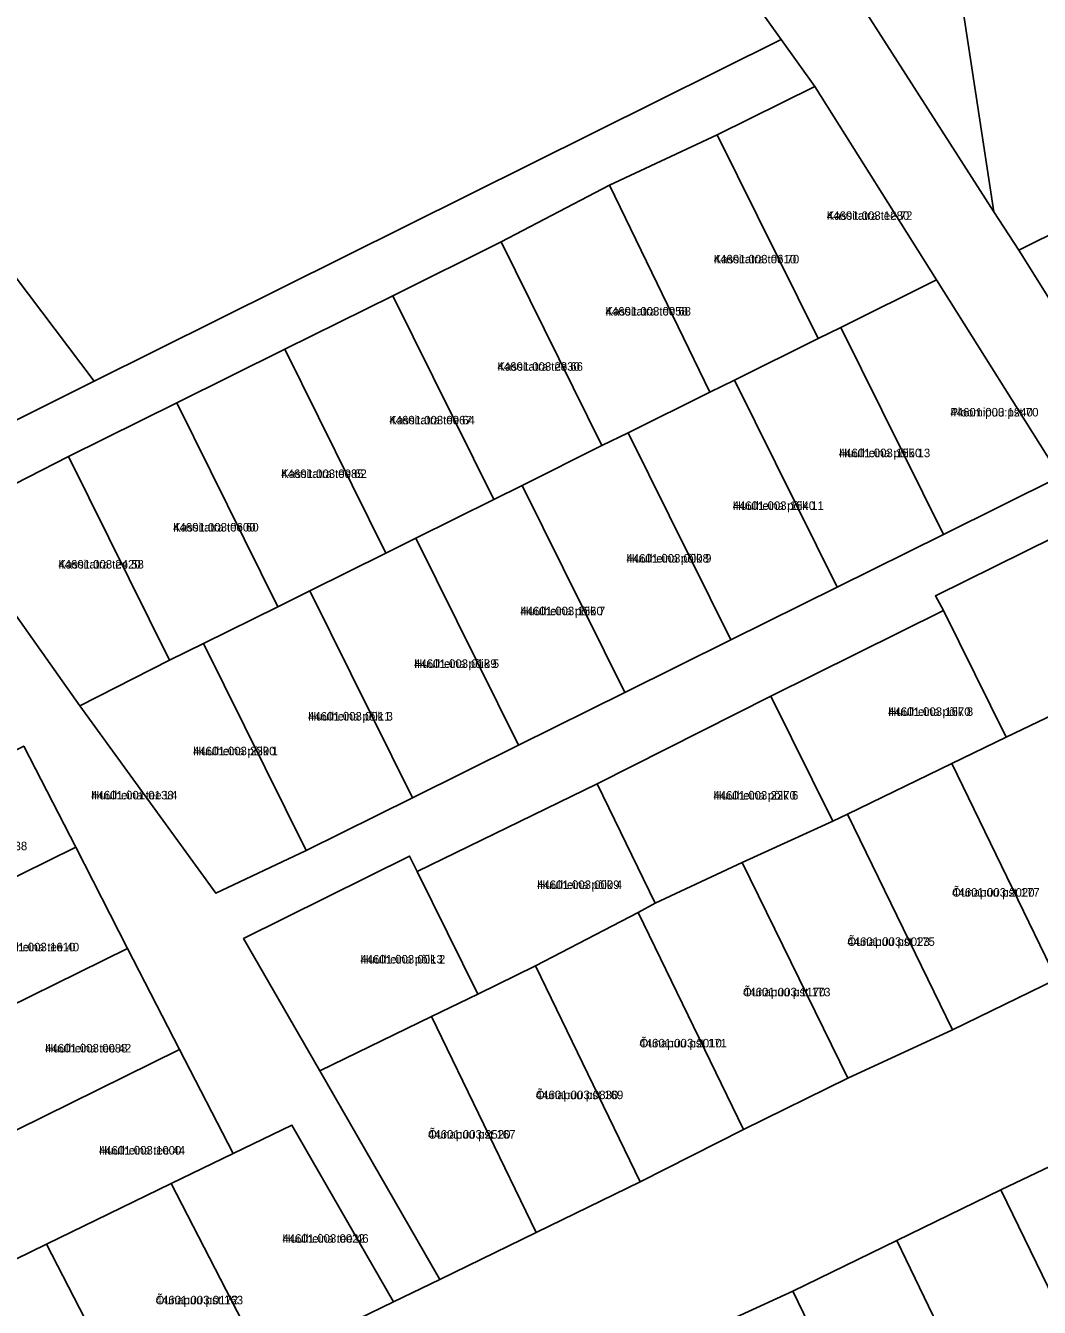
# Model space of a CAD drawing. Extents: x 551843 to 558501, y 6589003 to 6595718.
# Drawn here: x 553719.3 to 553897.7, y 6593355.7 to 6593581.1 of the extents above; entities that cross this region are included whole.
import ezdxf

# ---------------------------------------------------------------- set-up
doc = ezdxf.new("R2010")
doc.units = 0
for name, color, linetype in [('L_AADRESS', 7, 'Continuous'), ('PIIR', 7, 'Continuous'), ('TUNNUS', 7, 'Continuous')]:
    doc.layers.add(name, color=color, linetype=linetype)

msp = doc.modelspace()

# ---------------------------------------------------------------- linework, layer by layer
at = {"layer": 'PIIR'}
for points in [[(553642.95, 6593640.9), (553651.15, 6593647.15), (553652.31, 6593645.45), (553665.73, 6593654.61), (553682.25, 6593665.88), (553706.18, 6593691.1), (553727.55, 6593666.75), (553740.49, 6593651.51), (553753.74, 6593636.43), (553762.31, 6593626.44), (553803.44, 6593644.47), (553829.2, 6593610.91), (553852.28, 6593578.7), (553731.4, 6593518.62), (553696.7, 6593564.49), (553681.11, 6593583.74), (553684.34, 6593586.4), (553671.35, 6593603.22), (553668.55, 6593601.29), (553655.51, 6593620.23)], [(553910.99, 6593550.05), (553894.06, 6593541.63), (553889.7, 6593548.41), (553884.42, 6593582.9), (553904.35, 6593593.35)], [(553840.98, 6593561.94), (553858.18, 6593570.46), (553879.59, 6593536.42), (553862.74, 6593528.08), (553858.75, 6593526.1)], [(553696.7, 6593564.49), (553731.4, 6593518.62), (553702.86, 6593504.37), (553697.19, 6593505.23), (553669, 6593541.5)], [(553840.98, 6593561.94), (553858.75, 6593526.1), (553844.05, 6593518.81), (553839.73, 6593516.67), (553822.04, 6593553.06)], [(553894.06, 6593541.63), (553910.99, 6593550.05), (553915.92, 6593552.49), (553934.2, 6593561.55), (553942.87, 6593544.12), (553904.46, 6593525.08)], [(553802.98, 6593543.1), (553822.04, 6593553.06), (553839.73, 6593516.67), (553825.36, 6593509.55), (553820.74, 6593507.32)], [(553802.98, 6593543.1), (553820.74, 6593507.32), (553806.68, 6593500.28), (553801.7, 6593497.81), (553783.93, 6593533.64)], [(553862.74, 6593528.08), (553879.59, 6593536.42), (553901.33, 6593501.86), (553880.8, 6593491.68)], [(553764.93, 6593524.22), (553783.93, 6593533.64), (553801.7, 6593497.81), (553788, 6593491.02), (553782.7, 6593488.39)], [(553858.75, 6593526.1), (553862.74, 6593528.08), (553880.8, 6593491.68), (553862.11, 6593482.42), (553844.05, 6593518.81)], [(553763.69, 6593478.96), (553745.92, 6593514.79), (553764.93, 6593524.22), (553782.7, 6593488.39), (553769.33, 6593481.76)], [(553825.36, 6593509.55), (553839.73, 6593516.67), (553844.05, 6593518.81), (553862.11, 6593482.42), (553843.43, 6593473.16)], [(553726.89, 6593505.4), (553745.92, 6593514.79), (553763.69, 6593478.96), (553750.66, 6593472.5), (553744.66, 6593469.57)], [(553820.74, 6593507.32), (553825.36, 6593509.55), (553843.43, 6593473.16), (553824.75, 6593463.89), (553806.68, 6593500.28)], [(553726.89, 6593505.4), (553744.66, 6593469.57), (553728.88, 6593461.52), (553705.53, 6593494.44)], [(553788, 6593491.02), (553801.7, 6593497.81), (553806.68, 6593500.28), (553824.75, 6593463.89), (553806.07, 6593454.63)], [(553879.39, 6593480.86), (553905.64, 6593493.8), (553918.76, 6593469.05), (553900.31, 6593460.06), (553891.87, 6593456.03), (553880.81, 6593478.3)], [(553787.39, 6593445.37), (553769.33, 6593481.76), (553782.7, 6593488.39), (553788, 6593491.02), (553806.07, 6593454.63)], [(553763.69, 6593478.96), (553769.33, 6593481.76), (553787.39, 6593445.37), (553768.71, 6593436.11), (553750.66, 6593472.5)], [(553850.44, 6593463.25), (553880.81, 6593478.3), (553891.87, 6593456.03), (553882.26, 6593451.4), (553863.95, 6593442.5), (553861.37, 6593441.22)], [(553728.88, 6593461.52), (553744.66, 6593469.57), (553750.66, 6593472.5), (553768.71, 6593436.11), (553752.79, 6593428.57)], [(553830.12, 6593426.84), (553819.87, 6593447.79), (553850.44, 6593463.25), (553861.37, 6593441.22), (553845.4, 6593433.96)], [(553882.26, 6593451.4), (553891.87, 6593456.03), (553900.31, 6593460.06), (553919.02, 6593422.36), (553900.72, 6593413.45)], [(553680.76, 6593435.6), (553719.02, 6593454.46), (553728.16, 6593436.67), (553689.89, 6593417.81)], [(553863.95, 6593442.5), (553882.26, 6593451.4), (553900.72, 6593413.45), (553882.41, 6593404.55)], [(553819.87, 6593447.79), (553830.12, 6593426.84), (553827.11, 6593425.21), (553809.03, 6593415.79), (553798.91, 6593410.85), (553788.22, 6593432.4)], [(553861.37, 6593441.22), (553863.95, 6593442.5), (553882.41, 6593404.55), (553863.97, 6593396.03), (553845.4, 6593433.96)], [(553689.89, 6593417.81), (553728.16, 6593436.67), (553737.29, 6593418.88), (553699.03, 6593400.02)], [(553786.9, 6593435.09), (553788.22, 6593432.4), (553798.91, 6593410.85), (553790.72, 6593406.88), (553771.09, 6593397.33), (553757.69, 6593420.6)], [(553830.12, 6593426.84), (553845.4, 6593433.96), (553863.97, 6593396.03), (553845.62, 6593387.04), (553827.11, 6593425.21)], [(553809.03, 6593415.79), (553827.11, 6593425.21), (553845.62, 6593387.04), (553827.48, 6593377.84)], [(553737.29, 6593418.88), (553746.43, 6593401.09), (553708.24, 6593382.26), (553707.89, 6593382.93), (553699.03, 6593400.02)], [(553790.72, 6593406.88), (553798.91, 6593410.85), (553809.03, 6593415.79), (553827.48, 6593377.84), (553809.17, 6593368.93)], [(553790.72, 6593406.88), (553809.17, 6593368.93), (553792.19, 6593360.67), (553771.09, 6593397.33)], [(553708.24, 6593382.26), (553746.43, 6593401.09), (553755.85, 6593382.8), (553744.97, 6593377.51), (553723.03, 6593366.85), (553717.5, 6593364.16)], [(553755.85, 6593382.8), (553766.18, 6593387.81), (553784.07, 6593356.73), (553761.39, 6593345.7), (553744.97, 6593377.51)], [(553909.52, 6593385.26), (553926.91, 6593348.89), (553924.84, 6593347.89), (553908.6, 6593339.99), (553890.9, 6593376.42)], [(553739.43, 6593335.04), (553723.03, 6593366.85), (553744.97, 6593377.51), (553761.39, 6593345.7)], [(553872.59, 6593367.51), (553890.9, 6593376.42), (553908.6, 6593339.99), (553906.31, 6593338.87), (553890.23, 6593331.05)], [(553854.3, 6593358.62), (553872.59, 6593367.51), (553890.23, 6593331.05), (553887.78, 6593329.87), (553871.99, 6593322.18)], [(553701.02, 6593356.45), (553717.5, 6593364.16), (553723.03, 6593366.85), (553739.43, 6593335.04), (553717.06, 6593324.38)], [(553835.93, 6593350.16), (553854.3, 6593358.62), (553871.99, 6593322.18), (553869.25, 6593320.86), (553853.55, 6593313.74)]]:
    msp.add_lwpolyline(points, close=True, dxfattribs=at)
for points in [[(553978.42, 6593328.33), (553963.28, 6593366.56), (553948.16, 6593404.4), (553943.27, 6593414.35), (553937.73, 6593431.46), (553918.76, 6593469.05), (553905.64, 6593493.8), (553901.33, 6593501.86), (553879.59, 6593536.42), (553858.18, 6593570.46), (553852.28, 6593578.7), (553829.2, 6593610.91)], [(553866.47, 6593584.6), (553889.7, 6593548.41), (553894.06, 6593541.63), (553904.46, 6593525.08), (553915.42, 6593507.64), (553916.1, 6593506.56), (553925.29, 6593488.65), (553937.09, 6593466.57), (553952.07, 6593438.2), (553965.81, 6593422.58), (553962.85, 6593413.18), (553971.68, 6593386.65), (553980.29, 6593364.84), (553987.82, 6593345.77)], [(553884.42, 6593582.9), (553889.7, 6593548.41), (553866.47, 6593584.6)], [(553702.86, 6593504.37), (553731.4, 6593518.62), (553852.28, 6593578.7), (553858.18, 6593570.46), (553840.98, 6593561.94), (553822.04, 6593553.06), (553802.98, 6593543.1), (553783.93, 6593533.64), (553764.93, 6593524.22), (553745.92, 6593514.79), (553726.89, 6593505.4), (553705.53, 6593494.44), (553728.88, 6593461.52), (553752.79, 6593428.57), (553768.71, 6593436.11), (553787.39, 6593445.37), (553806.07, 6593454.63), (553824.75, 6593463.89), (553843.43, 6593473.16), (553862.11, 6593482.42), (553880.8, 6593491.68), (553901.33, 6593501.86)], [(553905.64, 6593493.8), (553879.39, 6593480.86), (553880.81, 6593478.3), (553850.44, 6593463.25), (553819.87, 6593447.79), (553788.22, 6593432.4), (553786.9, 6593435.09), (553757.69, 6593420.6), (553771.09, 6593397.33), (553792.19, 6593360.67), (553784.07, 6593356.73), (553766.18, 6593387.81), (553755.85, 6593382.8), (553746.43, 6593401.09), (553737.29, 6593418.88), (553728.16, 6593436.67), (553719.02, 6593454.46)], [(553761.39, 6593345.7), (553784.07, 6593356.73), (553792.19, 6593360.67), (553809.17, 6593368.93), (553827.48, 6593377.84), (553845.62, 6593387.04), (553863.97, 6593396.03), (553882.41, 6593404.55), (553900.72, 6593413.45), (553919.02, 6593422.36), (553937.73, 6593431.46), (553943.27, 6593414.35), (553935.54, 6593410.55), (553940.5, 6593400.47), (553927.51, 6593393.79), (553909.52, 6593385.26), (553890.9, 6593376.42), (553872.59, 6593367.51), (553854.3, 6593358.62), (553835.93, 6593350.16)]]:
    msp.add_lwpolyline(points, dxfattribs=at)

# ---------------------------------------------------------------- texts
at = {"layer": 'L_AADRESS'}
for s, p in [('Kassitatra tee 72', (553860.29, 6593546.99)), ('Kassitatra tee 70', (553840.39, 6593539.33)), ('Kassitatra tee 68', (553821.35, 6593530.16)), ('Kassitatra tee 66', (553802.34, 6593520.45)), ('Ploomipuu pst 70', (553882.04, 6593512.41)), ('Kassitatra tee 64', (553783.32, 6593511.02)), ('Huulheina põik 13', (553862.42, 6593505.25)), ('Kassitatra tee 62', (553764.31, 6593501.59)), ('Huulheina põik 11', (553843.73, 6593495.98)), ('Kassitatra tee 60', (553745.29, 6593492.18)), ('Kassitatra tee 58', (553725.09, 6593485.67)), ('Huulheina põik 9', (553825.05, 6593486.72)), ('Huulheina põik 7', (553806.38, 6593477.45)), ('Huulheina põik 5', (553787.7, 6593468.2)), ('Huulheina põik 3', (553769.02, 6593458.94)), ('Huulheina põik 8', (553871.09, 6593459.76)), ('Huulheina põik 1', (553748.8, 6593452.83)), ('Huulheina tee L4', (553730.88, 6593445.07)), ('Huulheina põik 6', (553840.34, 6593445.04)), ('Huulheina tee 38', (553704.46, 6593436.13)), ('Huulheina põik 4', (553809.33, 6593429.32)), ('Õunapuu pst 177', (553882.34, 6593427.97)), ('Huulheina tee 40', (553713.59, 6593418.35)), ('Õunapuu pst 175', (553863.9, 6593419.32)), ('Huulheina põik 2', (553778.23, 6593416.21)), ('Õunapuu pst 173', (553845.54, 6593410.44)), ('Õunapuu pst 171', (553827.32, 6593401.46)), ('Huulheina tee 42', (553722.76, 6593400.57)), ('Õunapuu pst 169', (553809.1, 6593392.36)), ('Õunapuu pst 167', (553790.13, 6593385.42)), ('Huulheina tee 44', (553732.24, 6593382.62)), ('Huulheina tee 46', (553764.52, 6593367.11)), ('Õunapuu pst 163', (553742.21, 6593356.28))]:
    msp.add_text(s, height=1.5, dxfattribs=at).set_placement(p)
at = {"layer": 'TUNNUS'}
for s, p in [('44601:003:1280', (553860.29, 6593546.99)), ('44601:003:0610', (553840.39, 6593539.33)), ('44601:003:0058', (553821.35, 6593530.16)), ('44601:003:2330', (553802.34, 6593520.45)), ('44601:003:1240', (553882.04, 6593512.41)), ('44601:003:0067', (553783.32, 6593511.02)), ('44601:003:1650', (553862.42, 6593505.25)), ('44601:003:0085', (553764.31, 6593501.59)), ('44601:003:1640', (553843.73, 6593495.98)), ('44601:003:0600', (553745.29, 6593492.18)), ('44601:003:2420', (553725.09, 6593485.67)), ('44601:003:0008', (553825.05, 6593486.72)), ('44601:003:1660', (553806.38, 6593477.45)), ('44601:003:0189', (553787.7, 6593468.2)), ('44601:003:0011', (553769.02, 6593458.94)), ('44601:003:1670', (553871.09, 6593459.76)), ('44601:003:2390', (553748.8, 6593452.83)), ('44601:001:0138', (553730.88, 6593445.07)), ('44601:003:2270', (553840.34, 6593445.04)), ('44601:003:0009', (553809.33, 6593429.32)), ('44601:003:2020', (553882.34, 6593427.97)), ('44601:003:1610', (553713.59, 6593418.35)), ('44601:003:0023', (553863.9, 6593419.32)), ('44601:003:0013', (553778.23, 6593416.21)), ('44601:003:1170', (553845.54, 6593410.44)), ('44601:003:0088', (553722.76, 6593400.57)), ('44601:003:2010', (553827.32, 6593401.46)), ('44601:003:0830', (553809.1, 6593392.36)), ('44601:003:2520', (553790.13, 6593385.42)), ('44601:003:1000', (553732.24, 6593382.62)), ('44601:003:0022', (553764.52, 6593367.11)), ('44601:003:0172', (553742.21, 6593356.28))]:
    msp.add_text(s, height=1.5, dxfattribs=at).set_placement(p)

doc.saveas('drawing.dxf')
